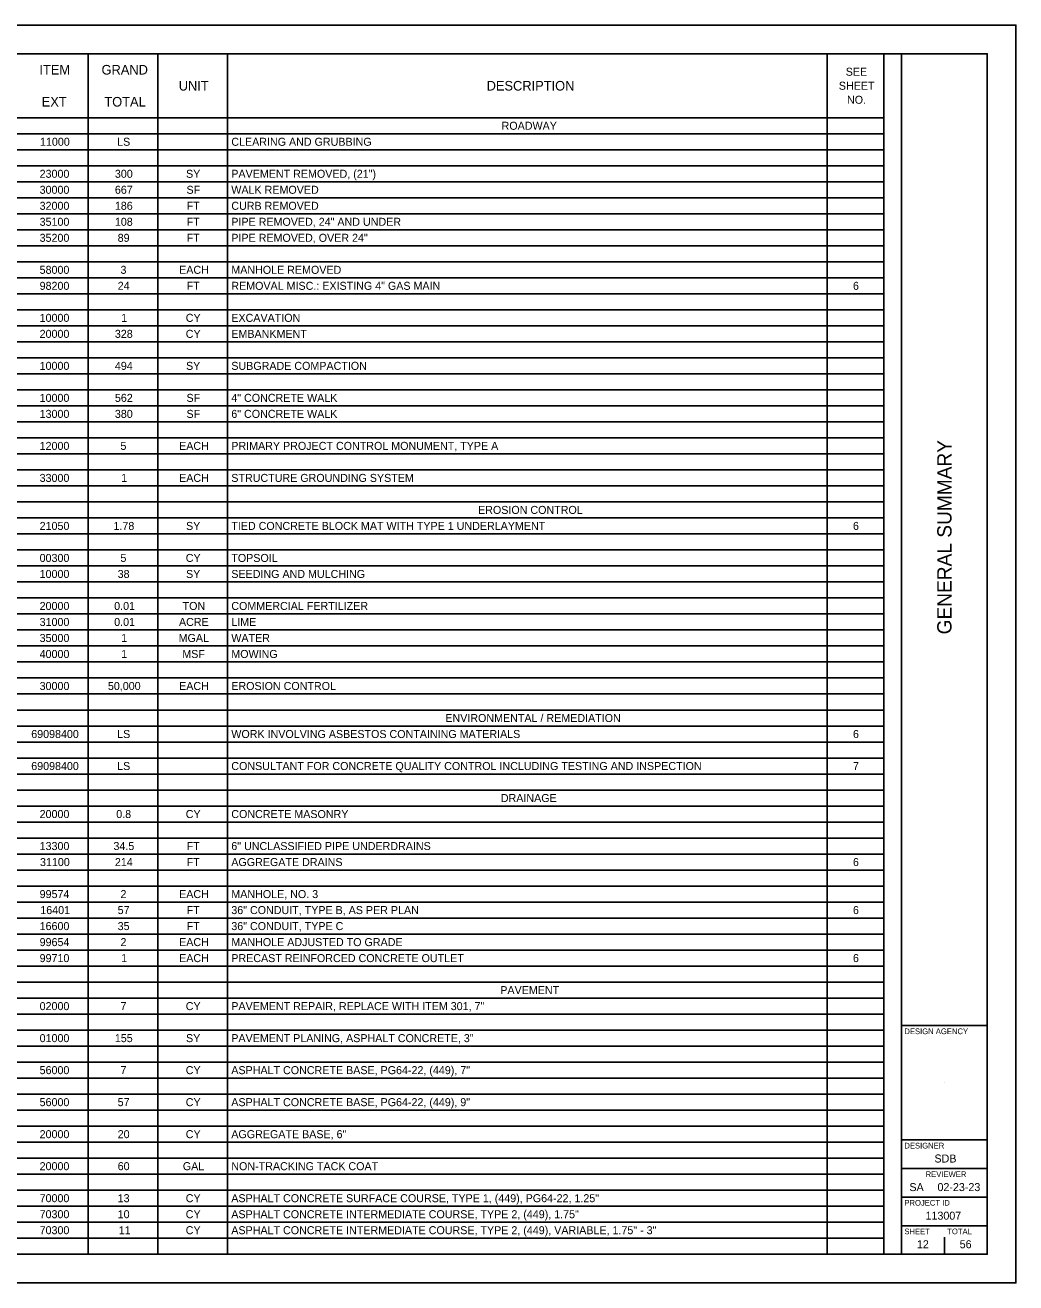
# Model space of a CAD drawing. Extents: x 0 to 34, y 0 to 22.
# Drawn here: x 16.67 to 34, y 0 to 22 of the extents above; entities that cross this region are included whole.
import ezdxf

# ---------------------------------------------------------------- set-up
doc = ezdxf.new("R2010")
doc.units = 0
for name, color, linetype in [('Default', 7, 'Continuous'), ('SH_Border', 7, 'Continuous'), ('SH_Cut_Line', 7, 'Continuous'), ('SH_Data', 7, 'Continuous')]:
    doc.layers.add(name, color=color, linetype=linetype)

msp = doc.modelspace()

# ---------------------------------------------------------------- linework, layer by layer
at = {"layer": 'Default'}
for p, q in [((1.5, 21.5), (31.68951, 21.5)), ((17.77236, 21.5), (17.77236, 0.50075)), ((18.99114, 21.5), (18.99114, 0.50075)), ((20.20992, 21.5), (20.20992, 0.50075)), ((30.70131, 21.5), (30.70131, 0.50075)), ((31.68951, 21.5), (31.68951, 0.50075)), ((1.5, 20.38004), (31.68951, 20.38004)), ((1.5, 20.10005), (31.68951, 20.10005)), ((1.5, 19.82006), (31.68951, 19.82006)), ((1.5, 19.54007), (31.68951, 19.54007)), ((1.5, 19.26008), (31.68951, 19.26008)), ((1.5, 18.98009), (31.68951, 18.98009)), ((1.5, 18.7001), (31.68951, 18.7001)), ((1.5, 18.42011), (31.68951, 18.42011)), ((1.5, 18.14012), (31.68951, 18.14012)), ((1.5, 17.86013), (31.68951, 17.86013)), ((1.5, 17.58014), (31.68951, 17.58014)), ((1.5, 17.30015), (31.68951, 17.30015)), ((1.5, 17.02016), (31.68951, 17.02016)), ((1.5, 16.74017), (31.68951, 16.74017)), ((1.5, 16.46018), (31.68951, 16.46018)), ((1.5, 16.18019), (31.68951, 16.18019)), ((1.5, 15.9002), (31.68951, 15.9002)), ((1.5, 15.62021), (31.68951, 15.62021)), ((1.5, 15.34022), (31.68951, 15.34022)), ((1.5, 15.06023), (31.68951, 15.06023)), ((1.5, 14.78024), (31.68951, 14.78024)), ((1.5, 14.50025), (31.68951, 14.50025)), ((1.5, 14.22026), (31.68951, 14.22026)), ((1.5, 13.94027), (31.68951, 13.94027)), ((1.5, 13.66028), (31.68951, 13.66028)), ((1.5, 13.38029), (31.68951, 13.38029)), ((1.5, 13.1003), (31.68951, 13.1003)), ((1.5, 12.82031), (31.68951, 12.82031)), ((1.5, 12.54032), (31.68951, 12.54032)), ((1.5, 12.26033), (31.68951, 12.26033)), ((1.5, 11.98034), (31.68951, 11.98034)), ((1.5, 11.70035), (31.68951, 11.70035)), ((1.5, 11.42036), (31.68951, 11.42036)), ((1.5, 11.14037), (31.68951, 11.14037)), ((1.5, 10.86038), (31.68951, 10.86038)), ((1.5, 10.58039), (31.68951, 10.58039)), ((1.5, 10.3004), (31.68951, 10.3004)), ((1.5, 10.02041), (31.68951, 10.02041)), ((1.5, 9.74042), (31.68951, 9.74042)), ((1.5, 9.46043), (31.68951, 9.46043)), ((1.5, 9.18044), (31.68951, 9.18044)), ((1.5, 8.90045), (31.68951, 8.90045)), ((1.5, 8.62046), (31.68951, 8.62046)), ((1.5, 8.34047), (31.68951, 8.34047)), ((1.5, 8.06048), (31.68951, 8.06048)), ((1.5, 7.78049), (31.68951, 7.78049)), ((1.5, 7.5005), (31.68951, 7.5005)), ((1.5, 7.22051), (31.68951, 7.22051)), ((1.5, 6.94052), (31.68951, 6.94052)), ((1.5, 6.66053), (31.68951, 6.66053)), ((1.5, 6.38054), (31.68951, 6.38054)), ((1.5, 6.10055), (31.68951, 6.10055)), ((1.5, 5.82056), (31.68951, 5.82056)), ((1.5, 5.54057), (31.68951, 5.54057)), ((1.5, 5.26058), (31.68951, 5.26058)), ((1.5, 4.98059), (31.68951, 4.98059)), ((1.5, 4.7006), (31.68951, 4.7006)), ((1.5, 4.42061), (31.68951, 4.42061)), ((1.5, 4.14062), (31.68951, 4.14062)), ((1.5, 3.86063), (31.68951, 3.86063)), ((1.5, 3.58064), (31.68951, 3.58064)), ((1.5, 3.30065), (31.68951, 3.30065)), ((1.5, 3.02066), (31.68951, 3.02066)), ((1.5, 2.74067), (31.68951, 2.74067)), ((1.5, 2.46068), (31.68951, 2.46068)), ((1.5, 2.18069), (31.68951, 2.18069)), ((1.5, 1.9007), (31.68951, 1.9007)), ((1.5, 1.62071), (31.68951, 1.62071)), ((1.5, 1.34072), (31.68951, 1.34072)), ((1.5, 1.06073), (31.68951, 1.06073)), ((1.5, 0.78074), (31.68951, 0.78074)), ((1.5, 0.50075), (31.68951, 0.50075))]:
    msp.add_line(p, q, dxfattribs=at)
at = {"layer": 'SH_Border'}
for p, q in [((32, 0.5), (32, 21.5)), ((32, 4.5), (33.5, 4.5)), ((32, 2.5), (33.5, 2.5)), ((32, 2), (33.5, 2)), ((32, 1.5), (33.5, 1.5)), ((32, 1), (33.5, 1))]:
    msp.add_line(p, q, dxfattribs=at)
msp.add_lwpolyline([(1.5, 21.5), (33.5, 21.5), (33.5, 0.5), (1.5, 0.5)], close=True, dxfattribs=at)
at = {"layer": 'SH_Cut_Line'}
msp.add_lwpolyline([(0, 0), (34, 0), (34, 22), (0, 22)], close=True, dxfattribs=at)
at = {"layer": 'SH_Data'}
for p, q in [((32.75, 3.5), (32.75, 3.5)), ((32.375, 0.675), (32.375, 0.675)), ((32.75, 0.5), (32.75, 0.8))]:
    msp.add_line(p, q, dxfattribs=at)

# ---------------------------------------------------------------- texts
at = {"layer": 'Default'}
for s, height, p in [('ITEM', 0.168, (16.918595, 21.13601)), ('GRAND', 0.168, (18.005882, 21.13601)), ('SEE ', 0.14, (31.023937, 21.11502)), ('UNIT', 0.168, (19.356213, 20.85602)), ('DESCRIPTION', 0.168, (24.742313, 20.85602)), ('SHEET ', 0.14, (30.903651, 20.87002)), ('EXT', 0.168, (16.959622, 20.57603)), ('TOTAL', 0.168, (18.054803, 20.57603)), ('NO.', 0.14, (31.046601, 20.62502)), ('ROADWAY', 0.14, (25.003811, 20.170045)), ('11000', 0.14, (16.929073, 19.890055)), ('LS', 0.14, (18.278703, 19.890055)), ('CLEARING AND GRUBBING', 0.14, (20.2758, 19.890055)), ('23000', 0.14, (16.922542, 19.330075)), ('300', 0.14, (18.239184, 19.330075)), ('SY', 0.14, (19.48375, 19.330075)), ('PAVEMENT REMOVED, (21")', 0.14, (20.2758, 19.330075)), ('30000', 0.14, (16.922542, 19.050085)), ('667', 0.14, (18.238944, 19.050085)), ('SF', 0.14, (19.492057, 19.050085)), ('WALK REMOVED', 0.14, (20.2758, 19.050085)), ('32000', 0.14, (16.922542, 18.770095)), ('186', 0.14, (18.238944, 18.770095)), ('FT', 0.14, (19.494746, 18.770095)), ('CURB REMOVED', 0.14, (20.2758, 18.770095)), ('35100', 0.14, (16.922542, 18.490105)), ('108', 0.14, (18.238848, 18.490105)), ('FT', 0.14, (19.494746, 18.490105)), ('PIPE REMOVED, 24" AND UNDER', 0.14, (20.2758, 18.490105)), ('35200', 0.14, (16.922542, 18.210115)), ('89', 0.14, (18.287778, 18.210115)), ('FT', 0.14, (19.494746, 18.210115)), ('PIPE REMOVED, OVER 24"', 0.14, (20.2758, 18.210115)), ('58000', 0.14, (16.922542, 17.650135)), ('3', 0.14, (18.336805, 17.650135)), ('EACH', 0.14, (19.363032, 17.650135)), ('MANHOLE REMOVED', 0.14, (20.2758, 17.650135)), ('98200', 0.14, (16.922542, 17.370145)), ('24', 0.14, (18.288162, 17.370145)), ('FT', 0.14, (19.494746, 17.370145)), ('REMOVAL MISC.: EXISTING 4" GAS MAIN', 0.14, (20.2758, 17.370145)), ('6', 0.14, (31.150465, 17.370145)), ('10000', 0.14, (16.922542, 16.810165)), ('1', 0.14, (18.349002, 16.810165)), ('CY', 0.14, (19.4789, 16.810165)), ('EXCAVATION', 0.14, (20.2758, 16.810165)), ('20000', 0.14, (16.922542, 16.530175)), ('328', 0.14, (18.238848, 16.530175)), ('CY', 0.14, (19.4789, 16.530175)), ('EMBANKMENT', 0.14, (20.2758, 16.530175)), ('10000', 0.14, (16.922542, 15.970195)), ('494', 0.14, (18.239232, 15.970195)), ('SY', 0.14, (19.48375, 15.970195)), ('SUBGRADE COMPACTION', 0.14, (20.2758, 15.970195)), ('10000', 0.14, (16.922542, 15.410215)), ('562', 0.14, (18.239616, 15.410215)), ('SF', 0.14, (19.492057, 15.410215)), ('4" CONCRETE WALK', 0.14, (20.2758, 15.410215)), ('13000', 0.14, (16.922542, 15.130225)), ('380', 0.14, (18.239184, 15.130225)), ('SF', 0.14, (19.492057, 15.130225)), ('6" CONCRETE WALK', 0.14, (20.2758, 15.130225)), ('12000', 0.14, (16.922542, 14.570245)), ('5', 0.14, (18.336325, 14.570245)), ('EACH', 0.14, (19.363032, 14.570245)), ('PRIMARY PROJECT CONTROL MONUMENT, TYPE A', 0.14, (20.2758, 14.570245)), ('33000', 0.14, (16.922542, 14.010265)), ('1', 0.14, (18.349002, 14.010265)), ('EACH', 0.14, (19.363032, 14.010265)), ('STRUCTURE GROUNDING SYSTEM', 0.14, (20.2758, 14.010265)), ('EROSION CONTROL', 0.14, (24.592582, 13.450285)), ('21050', 0.14, (16.922542, 13.170295)), ('1.78', 0.14, (18.214406, 13.170295)), ('SY', 0.14, (19.48375, 13.170295)), ('TIED CONCRETE BLOCK MAT WITH TYPE 1 UNDERLAYMENT', 0.14, (20.2758, 13.170295)), ('6', 0.14, (31.150465, 13.170295)), ('00300', 0.14, (16.922542, 12.610315)), ('5', 0.14, (18.336325, 12.610315)), ('CY', 0.14, (19.4789, 12.610315)), ('TOPSOIL', 0.14, (20.2758, 12.610315)), ('10000', 0.14, (16.922542, 12.330325)), ('38', 0.14, (18.287778, 12.330325)), ('SY', 0.14, (19.48375, 12.330325)), ('SEEDING AND MULCHING', 0.14, (20.2758, 12.330325)), ('20000', 0.14, (16.922542, 11.770345)), ('0.01', 0.14, (18.226699, 11.770345)), ('TON', 0.14, (19.423487, 11.770345)), ('COMMERCIAL FERTILIZER', 0.14, (20.2758, 11.770345)), ('31000', 0.14, (16.922542, 11.490355)), ('0.01', 0.14, (18.226699, 11.490355)), ('ACRE', 0.14, (19.360631, 11.490355)), ('LIME', 0.14, (20.2758, 11.490355)), ('35000', 0.14, (16.922542, 11.210365)), ('1', 0.14, (18.349002, 11.210365)), ('MGAL', 0.14, (19.354196, 11.210365)), ('WATER', 0.14, (20.2758, 11.210365)), ('40000', 0.14, (16.922542, 10.930375)), ('1', 0.14, (18.349002, 10.930375)), ('MSF', 0.14, (19.418733, 10.930375)), ('MOWING', 0.14, (20.2758, 10.930375)), ('30000', 0.14, (16.922542, 10.370395)), ('50,000', 0.14, (18.116881, 10.370395)), ('EACH', 0.14, (19.363032, 10.370395)), ('EROSION CONTROL', 0.14, (20.2758, 10.370395)), ('ENVIRONMENTAL / REMEDIATION', 0.14, (24.019916, 9.810415)), ('69098400', 0.14, (16.77575, 9.530425)), ('LS', 0.14, (18.278703, 9.530425)), ('WORK INVOLVING ASBESTOS CONTAINING MATERIALS', 0.14, (20.2758, 9.530425)), ('6', 0.14, (31.150465, 9.530425)), ('69098400', 0.14, (16.77575, 8.970445)), ('LS', 0.14, (18.278703, 8.970445)), ('CONSULTANT FOR CONCRETE QUALITY CONTROL INCLUDING TESTING AND INSPECTION', 0.14, (20.2758, 8.970445)), ('7', 0.14, (31.150465, 8.970445)), ('DRAINAGE', 0.14, (24.990462, 8.410465)), ('20000', 0.14, (16.922542, 8.130475)), ('0.8', 0.14, (18.263337, 8.130475)), ('CY', 0.14, (19.4789, 8.130475)), ('CONCRETE MASONRY', 0.14, (20.2758, 8.130475)), ('13300', 0.14, (16.922542, 7.570495)), ('34.5', 0.14, (18.214022, 7.570495)), ('FT', 0.14, (19.494746, 7.570495)), ('6" UNCLASSIFIED PIPE UNDERDRAINS', 0.14, (20.2758, 7.570495)), ('31100', 0.14, (16.929073, 7.290505)), ('214', 0.14, (18.239232, 7.290505)), ('FT', 0.14, (19.494746, 7.290505)), ('AGGREGATE DRAINS', 0.14, (20.2758, 7.290505)), ('6', 0.14, (31.150465, 7.290505)), ('99574', 0.14, (16.92259, 6.730525)), ('2', 0.14, (18.337477, 6.730525)), ('EACH', 0.14, (19.363032, 6.730525)), ('MANHOLE, NO. 3', 0.14, (20.2758, 6.730525)), ('16401', 0.14, (16.934499, 6.450535)), ('57', 0.14, (18.287874, 6.450535)), ('FT', 0.14, (19.494746, 6.450535)), ('36" CONDUIT, TYPE B, AS PER PLAN', 0.14, (20.2758, 6.450535)), ('6', 0.14, (31.150465, 6.450535)), ('16600', 0.14, (16.922542, 6.170545)), ('35', 0.14, (18.287394, 6.170545)), ('FT', 0.14, (19.494746, 6.170545)), ('36" CONDUIT, TYPE C', 0.14, (20.2758, 6.170545)), ('99654', 0.14, (16.92259, 5.890555)), ('2', 0.14, (18.337477, 5.890555)), ('EACH', 0.14, (19.363032, 5.890555)), ('MANHOLE ADJUSTED TO GRADE', 0.14, (20.2758, 5.890555)), ('99710', 0.14, (16.922542, 5.610565)), ('1', 0.14, (18.349002, 5.610565)), ('EACH', 0.14, (19.363032, 5.610565)), ('PRECAST REINFORCED CONCRETE OUTLET', 0.14, (20.2758, 5.610565)), ('6', 0.14, (31.150465, 5.610565)), ('PAVEMENT', 0.14, (24.981338, 5.050585)), ('02000', 0.14, (16.922542, 4.770595)), ('7', 0.14, (18.336805, 4.770595)), ('CY', 0.14, (19.4789, 4.770595)), ('PAVEMENT REPAIR, REPLACE WITH ITEM 301, 7"', 0.14, (20.2758, 4.770595)), ('01000', 0.14, (16.922542, 4.210615)), ('155', 0.14, (18.238463, 4.210615)), ('SY', 0.14, (19.48375, 4.210615)), ('PAVEMENT PLANING, ASPHALT CONCRETE, 3"', 0.14, (20.2758, 4.210615)), ('56000', 0.14, (16.922542, 3.650635)), ('7', 0.14, (18.336805, 3.650635)), ('CY', 0.14, (19.4789, 3.650635)), ('ASPHALT CONCRETE BASE, PG64-22, (449), 7"', 0.14, (20.2758, 3.650635)), ('56000', 0.14, (16.922542, 3.090655)), ('57', 0.14, (18.287874, 3.090655)), ('CY', 0.14, (19.4789, 3.090655)), ('ASPHALT CONCRETE BASE, PG64-22, (449), 9"', 0.14, (20.2758, 3.090655)), ('20000', 0.14, (16.922542, 2.530675)), ('20', 0.14, (18.288114, 2.530675)), ('CY', 0.14, (19.4789, 2.530675)), ('AGGREGATE BASE, 6"', 0.14, (20.2758, 2.530675)), ('20000', 0.14, (16.922542, 1.970695)), ('60', 0.14, (18.288114, 1.970695)), ('GAL', 0.14, (19.42752, 1.970695)), ('NON-TRACKING TACK COAT', 0.14, (20.2758, 1.970695)), ('70000', 0.14, (16.922542, 1.410715)), ('13', 0.14, (18.287874, 1.410715)), ('CY', 0.14, (19.4789, 1.410715)), ('ASPHALT CONCRETE SURFACE COURSE, TYPE 1, (449), PG64-22, 1.25"', 0.14, (20.2758, 1.410715)), ('70300', 0.14, (16.922542, 1.130725)), ('10', 0.14, (18.288114, 1.130725)), ('CY', 0.14, (19.4789, 1.130725)), ('ASPHALT CONCRETE INTERMEDIATE COURSE, TYPE 2, (449), 1.75"', 0.14, (20.2758, 1.130725)), ('70300', 0.14, (16.922542, 0.850735)), ('11', 0.14, (18.306601, 0.850735)), ('CY', 0.14, (19.4789, 0.850735)), ('ASPHALT CONCRETE INTERMEDIATE COURSE, TYPE 2, (449), VARIABLE, 1.75" - 3"', 0.14, (20.2758, 0.850735))]:
    msp.add_text(s, height=height, dxfattribs=at).set_placement(p)
at = {"layer": 'SH_Data'}
msp.add_text('GENERAL SUMMARY', height=0.25, rotation=90, dxfattribs=at).set_placement((32.875, 11.343545))
for s, height, p in [('DESIGN AGENCY', 0.1, (32.05, 4.35)), ('DESIGNER', 0.1, (32.05, 2.35)), ('SDB', 0.14, (32.576282, 2.105)), ('REVIEWER', 0.1, (32.421831, 1.85)), ('SA', 0.14, (32.138197, 1.605)), ('02-23-23', 0.14, (32.628925, 1.605)), ('PROJECT ID', 0.1, (32.05, 1.35)), ('113007', 0.14, (32.41985, 1.105)), ('SHEET', 0.1, (32.05, 0.85)), ('TOTAL', 0.1, (32.8, 0.85)), ('12', 0.14, (32.269376, 0.605)), ('56', 0.14, (33.017601, 0.605))]:
    msp.add_text(s, height=height, dxfattribs=at).set_placement(p)

doc.saveas('drawing.dxf')
